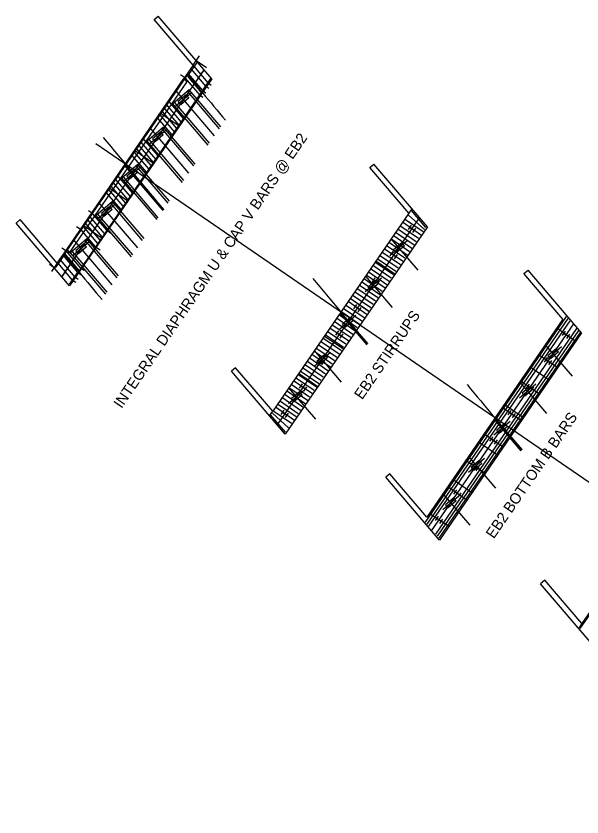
# Model space of a CAD drawing. Extents: x 2378999 to 2381348, y 331302 to 333122.
# Drawn here: x 2379375.1 to 2379481.1, y 331862.8 to 332012.7 of the extents above; entities that cross this region are included whole.
import ezdxf

# ---------------------------------------------------------------- set-up
doc = ezdxf.new("R2010")
doc.units = 0
for name, color, linetype in [('Arrowhead Terminators', 7, 'Continuous'), ('Arrowhead Terminators CELL', 7, 'Continuous'), ('Dimension Lines', 7, 'Continuous'), ('Dimension Lines CELL', 7, 'Continuous'), ('Mis Work Point CELL', 7, 'Continuous'), ('P_NCDOT_Horizontal_Alignment', 7, 'Continuous'), ('P_SMU_Approach_Slab', 7, 'Continuous'), ('P_SMU_Bent_Cap', 7, 'Continuous'), ('P_SMU_Concrete_Barrier_Rail', 7, 'Continuous'), ('P_SMU_D_Deck_Outline', 7, 'Continuous'), ('P_SMU_Deck', 7, 'Continuous'), ('P_SMU_Girder_Concrete', 7, 'Continuous'), ('P_SMU_Mis_L_Lines', 7, 'Continuous'), ('P_SMU_Mis_Long_Chord', 7, 'Continuous'), ('P_SMU_Rebar_B_Bar', 7, 'Continuous'), ('P_SMU_Rebar_K_Bar', 7, 'Continuous'), ('P_SMU_Rebar_U_Bar', 7, 'Continuous'), ('Plan Sheet CELL', 7, 'Continuous'), ('Rebar Lines', 7, 'Continuous'), ('Scratch_Level_0', 7, 'Continuous'), ('Sup Concrete Slab Lines', 7, 'Continuous')]:
    doc.layers.add(name, color=color, linetype=linetype)

msp = doc.modelspace()

# ---------------------------------------------------------------- linework, layer by layer
at = {"layer": 'Arrowhead Terminators'}
for p, q in [((2379451.74, 331917.97), (2379478.16, 331956.43)), ((2379452.06, 331917.6), (2379478.48, 331956.06)), ((2379452.4, 331917.21), (2379478.82, 331955.66)), ((2379480.05, 331954.22), (2379453.63, 331915.77)), ((2379480.38, 331953.83), (2379453.96, 331915.37)), ((2379480.7, 331953.45), (2379454.28, 331915)), ((2379480.71, 331898.07), (2379507.13, 331936.52))]:
    msp.add_line(p, q, dxfattribs=at)
at = {"layer": 'Arrowhead Terminators CELL'}
msp.add_line((2379481.01, 331899), (2379480.43, 331898.15), dxfattribs=at)
at = {"layer": 'Dimension Lines'}
for p, q in [((2379408.29, 332003.47), (2379409.49, 332005.22)), ((2379408.88, 332004.33), (2379410.77, 332003.02)), ((2379406.83, 332001.05), (2379405.95, 332001.66)), ((2379410.65, 331999.55), (2379411.25, 331999.14)), ((2379411.08, 332000.17), (2379411.67, 331999.76)), ((2379409.52, 331997.9), (2379410.12, 331997.5)), ((2379410.09, 331998.73), (2379410.68, 331998.32)), ((2379389.44, 331975.74), (2379388.69, 331976.25)), ((2379451.59, 331972.74), (2379448.6, 331975.44)), ((2379451.86, 331973.13), (2379449.17, 331976.28)), ((2379448.02, 331974.61), (2379451.32, 331972.34)), ((2379387.32, 331972.65), (2379386.43, 331973.26)), ((2379392.13, 331972.59), (2379392.99, 331972.01)), ((2379446.32, 331972.13), (2379449.62, 331969.87)), ((2379446.75, 331972.75), (2379450.04, 331970.49)), ((2379447.17, 331973.37), (2379450.47, 331971.11)), ((2379445.47, 331970.9), (2379448.77, 331968.63)), ((2379445.9, 331971.52), (2379449.2, 331969.25)), ((2379384.58, 331968.67), (2379383.73, 331969.26)), ((2379390.01, 331969.5), (2379390.86, 331968.92)), ((2379444.62, 331969.66), (2379447.92, 331967.4)), ((2379445.05, 331970.28), (2379448.35, 331968.01)), ((2379443.35, 331967.81), (2379446.65, 331965.54)), ((2379443.77, 331968.42), (2379447.07, 331966.16)), ((2379382.26, 331965.59), (2379381.41, 331966.17)), ((2379382.85, 331966.44), (2379381.77, 331964.88)), ((2379442.08, 331965.95), (2379445.37, 331963.69)), ((2379442.5, 331966.57), (2379445.8, 331964.31)), ((2379442.93, 331967.19), (2379446.22, 331964.92)), ((2379386.71, 331964.7), (2379387.3, 331964.29)), ((2379387.27, 331965.52), (2379387.87, 331965.12)), ((2379441.23, 331964.72), (2379444.52, 331962.45)), ((2379441.65, 331965.33), (2379444.95, 331963.07)), ((2379385.72, 331963.26), (2379386.31, 331962.85)), ((2379386.14, 331963.88), (2379386.74, 331963.47)), ((2379440.38, 331963.48), (2379443.67, 331961.21)), ((2379439.1, 331961.63), (2379442.4, 331959.36)), ((2379439.53, 331962.24), (2379442.82, 331959.98)), ((2379439.95, 331962.86), (2379443.25, 331960.6)), ((2379438.25, 331960.39), (2379441.55, 331958.12)), ((2379438.68, 331961.01), (2379441.98, 331958.74)), ((2379436.98, 331958.53), (2379440.28, 331956.27)), ((2379437.83, 331959.77), (2379441.13, 331957.51)), ((2379436.13, 331957.3), (2379439.43, 331955.03)), ((2379436.55, 331957.92), (2379439.85, 331955.65)), ((2379434.86, 331955.44), (2379438.15, 331953.18)), ((2379435.28, 331956.06), (2379438.58, 331953.8)), ((2379435.71, 331956.68), (2379439, 331954.41)), ((2379434.43, 331954.83), (2379437.73, 331952.56)), ((2379433.16, 331952.97), (2379436.45, 331950.71)), ((2379433.58, 331953.59), (2379436.88, 331951.32)), ((2379431.88, 331951.12), (2379435.18, 331948.85)), ((2379432.31, 331951.73), (2379435.6, 331949.47)), ((2379432.73, 331952.35), (2379436.03, 331950.09)), ((2379431.03, 331949.88), (2379434.33, 331947.61)), ((2379431.46, 331950.5), (2379434.76, 331948.23)), ((2379429.76, 331948.03), (2379433.06, 331945.76)), ((2379430.18, 331948.64), (2379433.48, 331946.38)), ((2379428.91, 331946.79), (2379432.21, 331944.52)), ((2379429.33, 331947.41), (2379432.63, 331945.14)), ((2379428.06, 331945.55), (2379431.36, 331943.29)), ((2379428.49, 331946.17), (2379431.78, 331943.91)), ((2379426.79, 331943.7), (2379430.08, 331941.43)), ((2379427.64, 331944.93), (2379430.93, 331942.67)), ((2379425.94, 331942.46), (2379429.23, 331940.2)), ((2379426.36, 331943.08), (2379429.66, 331940.82)), ((2379424.66, 331940.61), (2379427.96, 331938.34)), ((2379425.09, 331941.23), (2379428.38, 331938.96)), ((2379425.51, 331941.84), (2379428.81, 331939.58)), ((2379424.24, 331939.99), (2379427.54, 331937.72)), ((2379425.54, 331934.82), (2379422.85, 331937.97)), ((2379426.11, 331935.65), (2379423.12, 331938.36)), ((2379423.39, 331938.75), (2379426.69, 331936.49))]:
    msp.add_line(p, q, dxfattribs=at)
at = {"layer": 'Dimension Lines CELL'}
msp.add_line((2379573.4, 331862.84), (2379390.08, 331988.78), dxfattribs=at)
at = {"layer": 'Mis Work Point CELL'}
for p, q in [((2379383.72, 331963.88), (2379410.33, 332002.62)), ((2379424.05, 331936.18), (2379450.66, 331974.92)), ((2379452.91, 331916.34), (2379479.53, 331955.08))]:
    msp.add_line(p, q, dxfattribs=at)
at = {"layer": 'P_NCDOT_Horizontal_Alignment'}
msp.add_arc((2384828.54, 336524.76), 7080, 219.900348, 219.972766, dxfattribs=at)
at = {"layer": 'P_SMU_Approach_Slab'}
msp.add_line((2379385.17, 331968.36), (2379407.13, 332000.31), dxfattribs=at)
for radius, start, end in [(7061.33, 219.839771, 219.846793), (7098.67, 219.924281, 219.931263)]:
    msp.add_arc((2384828.54, 336524.76), radius, start, end, dxfattribs=at)
at = {"layer": 'P_SMU_Bent_Cap'}
for p, q in [((2379408, 331998.31), (2379404.96, 331995.71)), ((2379403.21, 331991.34), (2379400.17, 331988.75)), ((2379398.43, 331984.37), (2379395.38, 331981.78)), ((2379393.64, 331977.41), (2379390.6, 331974.81)), ((2379388.85, 331970.44), (2379385.81, 331967.84)), ((2379448.33, 331970.61), (2379445.29, 331968.01)), ((2379443.54, 331963.64), (2379440.5, 331961.04)), ((2379438.75, 331956.67), (2379435.71, 331954.07)), ((2379433.96, 331949.7), (2379430.92, 331947.1)), ((2379477.2, 331950.77), (2379474.15, 331948.17)), ((2379472.41, 331943.8), (2379469.37, 331941.21)), ((2379429.18, 331942.73), (2379426.14, 331940.13)), ((2379467.62, 331936.83), (2379464.58, 331934.24)), ((2379462.83, 331929.87), (2379459.79, 331927.27)), ((2379458.04, 331922.9), (2379455, 331920.3))]:
    msp.add_line(p, q, dxfattribs=at)
at = {"layer": 'P_SMU_Concrete_Barrier_Rail'}
for radius, start, end in [(7060.38, 219.837589, 219.874109), (7060.38, 219.874109, 219.928485), (7099.63, 219.926438, 219.96274), (7099.63, 219.96274, 220.016792)]:
    msp.add_arc((2384828.54, 336524.76), radius, start, end, dxfattribs=at)
at = {"layer": 'P_SMU_D_Deck_Outline'}
for p, q in [((2379407, 331997.95), (2379405.48, 331996.65)), ((2379407.48, 331997.38), (2379407, 331997.95)), ((2379405.96, 331996.08), (2379405.48, 331996.65)), ((2379407.48, 331997.38), (2379405.96, 331996.08)), ((2379402.21, 331990.98), (2379400.69, 331989.68)), ((2379402.7, 331990.41), (2379401.18, 331989.11)), ((2379402.7, 331990.41), (2379402.21, 331990.98)), ((2379401.18, 331989.11), (2379400.69, 331989.68)), ((2379397.42, 331984.01), (2379395.9, 331982.71)), ((2379397.91, 331983.44), (2379397.42, 331984.01)), ((2379396.39, 331982.14), (2379395.9, 331982.71)), ((2379397.91, 331983.44), (2379396.39, 331982.14)), ((2379392.63, 331977.04), (2379391.11, 331975.74)), ((2379393.12, 331976.47), (2379391.6, 331975.17)), ((2379393.12, 331976.47), (2379392.63, 331977.04)), ((2379391.6, 331975.17), (2379391.11, 331975.74)), ((2379387.85, 331970.07), (2379386.33, 331968.77)), ((2379388.33, 331969.5), (2379386.81, 331968.2)), ((2379388.33, 331969.5), (2379387.85, 331970.07)), ((2379447.32, 331970.24), (2379445.8, 331968.94)), ((2379446.29, 331968.37), (2379445.8, 331968.94)), ((2379447.81, 331969.67), (2379446.29, 331968.37)), ((2379447.81, 331969.67), (2379447.32, 331970.24)), ((2379386.81, 331968.2), (2379386.33, 331968.77)), ((2379442.54, 331963.27), (2379441.02, 331961.97)), ((2379443.02, 331962.7), (2379442.54, 331963.27)), ((2379441.5, 331961.4), (2379441.02, 331961.97)), ((2379443.02, 331962.7), (2379441.5, 331961.4)), ((2379437.75, 331956.3), (2379436.23, 331955)), ((2379438.24, 331955.73), (2379436.71, 331954.43)), ((2379438.24, 331955.73), (2379437.75, 331956.3)), ((2379436.71, 331954.43), (2379436.23, 331955)), ((2379476.19, 331950.41), (2379474.67, 331949.11)), ((2379476.68, 331949.84), (2379475.16, 331948.54)), ((2379476.68, 331949.84), (2379476.19, 331950.41)), ((2379432.96, 331949.34), (2379431.44, 331948.04)), ((2379431.93, 331947.47), (2379431.44, 331948.04)), ((2379433.45, 331948.77), (2379431.93, 331947.47)), ((2379433.45, 331948.77), (2379432.96, 331949.34)), ((2379475.16, 331948.54), (2379474.67, 331949.11)), ((2379428.17, 331942.37), (2379426.65, 331941.07)), ((2379428.66, 331941.8), (2379428.17, 331942.37)), ((2379471.4, 331943.44), (2379469.88, 331942.14)), ((2379470.37, 331941.57), (2379469.88, 331942.14)), ((2379471.89, 331942.87), (2379470.37, 331941.57)), ((2379471.89, 331942.87), (2379471.4, 331943.44)), ((2379427.14, 331940.5), (2379426.65, 331941.07)), ((2379428.66, 331941.8), (2379427.14, 331940.5)), ((2379466.62, 331936.47), (2379465.1, 331935.17)), ((2379467.1, 331935.9), (2379466.62, 331936.47)), ((2379465.58, 331934.6), (2379465.1, 331935.17)), ((2379467.1, 331935.9), (2379465.58, 331934.6)), ((2379461.83, 331929.5), (2379460.31, 331928.2)), ((2379462.32, 331928.93), (2379460.8, 331927.63)), ((2379462.32, 331928.93), (2379461.83, 331929.5)), ((2379460.8, 331927.63), (2379460.31, 331928.2)), ((2379457.04, 331922.53), (2379455.52, 331921.23)), ((2379457.53, 331921.96), (2379457.04, 331922.53)), ((2379456.01, 331920.66), (2379455.52, 331921.23)), ((2379457.53, 331921.96), (2379456.01, 331920.66))]:
    msp.add_line(p, q, dxfattribs=at)
at = {"layer": 'P_SMU_Deck'}
for p, q in [((2379407.54, 331998.85), (2379404.5, 331996.25)), ((2379413.21, 331991.58), (2379407.22, 331998.58)), ((2379413.45, 331991.93), (2379407.54, 331998.85)), ((2379411.1, 331988.52), (2379404.5, 331996.25)), ((2379411.35, 331988.88), (2379404.82, 331996.52)), ((2379402.75, 331991.88), (2379399.71, 331989.28)), ((2379408.42, 331984.61), (2379402.44, 331991.61)), ((2379408.66, 331984.97), (2379402.75, 331991.88)), ((2379406.32, 331981.55), (2379399.71, 331989.28)), ((2379406.56, 331981.91), (2379400.03, 331989.55)), ((2379397.96, 331984.91), (2379394.92, 331982.32)), ((2379403.63, 331977.64), (2379397.65, 331984.64)), ((2379403.87, 331978), (2379397.96, 331984.91)), ((2379401.77, 331974.94), (2379395.24, 331982.59)), ((2379401.53, 331974.58), (2379394.92, 331982.32)), ((2379393.18, 331977.94), (2379390.14, 331975.35)), ((2379399.09, 331971.03), (2379393.18, 331977.94)), ((2379398.84, 331970.67), (2379392.86, 331977.67)), ((2379396.74, 331967.62), (2379390.14, 331975.35)), ((2379396.99, 331967.97), (2379390.45, 331975.62)), ((2379388.39, 331970.98), (2379385.35, 331968.38)), ((2379394.05, 331963.7), (2379388.07, 331970.71)), ((2379394.3, 331964.06), (2379388.39, 331970.98)), ((2379391.95, 331960.65), (2379385.35, 331968.38)), ((2379392.2, 331961), (2379385.67, 331968.65))]:
    msp.add_line(p, q, dxfattribs=at)
at = {"layer": 'P_SMU_Girder_Concrete'}
for p, q in [((2379448.56, 331972.72), (2379449.12, 331973.55)), ((2379448.84, 331973.13), (2379449.65, 331972.58)), ((2379449.37, 331972.17), (2379449.93, 331972.99)), ((2379445.16, 331967.78), (2379445.73, 331968.6)), ((2379445.44, 331968.19), (2379446.25, 331967.63)), ((2379445.97, 331967.22), (2379446.54, 331968.04)), ((2379441.76, 331962.83), (2379442.33, 331963.66)), ((2379442.05, 331963.24), (2379442.86, 331962.69)), ((2379442.57, 331962.27), (2379443.14, 331963.1)), ((2379438.36, 331957.89), (2379438.93, 331958.71)), ((2379438.65, 331958.3), (2379439.46, 331957.74)), ((2379439.17, 331957.33), (2379439.74, 331958.15)), ((2379434.97, 331952.94), (2379435.53, 331953.77)), ((2379435.25, 331953.35), (2379436.06, 331952.8)), ((2379435.78, 331952.38), (2379436.34, 331953.21)), ((2379477.43, 331952.89), (2379477.99, 331953.71)), ((2379477.71, 331953.3), (2379478.52, 331952.74)), ((2379478.24, 331952.33), (2379478.8, 331953.16)), ((2379431.57, 331948), (2379432.14, 331948.82)), ((2379431.85, 331948.41), (2379432.66, 331947.85)), ((2379432.38, 331947.44), (2379432.95, 331948.26)), ((2379474.03, 331947.94), (2379474.59, 331948.77)), ((2379474.31, 331948.36), (2379475.12, 331947.8)), ((2379474.84, 331947.39), (2379475.4, 331948.21)), ((2379428.17, 331943.05), (2379428.74, 331943.87)), ((2379428.45, 331943.46), (2379429.27, 331942.91)), ((2379470.63, 331943), (2379471.2, 331943.82)), ((2379428.98, 331942.49), (2379429.55, 331943.32)), ((2379470.91, 331943.41), (2379471.72, 331942.85)), ((2379471.44, 331942.44), (2379472.01, 331943.27)), ((2379424.77, 331938.1), (2379425.34, 331938.93)), ((2379425.06, 331938.52), (2379425.87, 331937.96)), ((2379425.58, 331937.55), (2379426.15, 331938.37)), ((2379467.23, 331938.05), (2379467.8, 331938.88)), ((2379467.52, 331938.46), (2379468.33, 331937.91)), ((2379468.04, 331937.5), (2379468.61, 331938.32)), ((2379463.83, 331933.11), (2379464.4, 331933.93)), ((2379464.12, 331933.52), (2379464.93, 331932.96)), ((2379464.65, 331932.55), (2379465.21, 331933.37)), ((2379460.44, 331928.16), (2379461, 331928.99)), ((2379460.72, 331928.57), (2379461.53, 331928.02)), ((2379461.25, 331927.61), (2379461.81, 331928.43)), ((2379457.04, 331923.22), (2379457.61, 331924.04)), ((2379457.32, 331923.63), (2379458.13, 331923.07)), ((2379457.85, 331922.66), (2379458.42, 331923.48)), ((2379453.64, 331918.27), (2379454.21, 331919.1)), ((2379453.92, 331918.68), (2379454.74, 331918.13)), ((2379454.45, 331917.71), (2379455.02, 331918.54))]:
    msp.add_line(p, q, dxfattribs=at)
at = {"layer": 'P_SMU_Mis_L_Lines'}
for p, q in [((2379412.28, 331990.23), (2379405.02, 331998.72)), ((2379407.49, 331983.26), (2379400.24, 331991.75)), ((2379402.7, 331976.29), (2379395.45, 331984.78)), ((2379397.91, 331969.32), (2379390.66, 331977.81)), ((2379393.13, 331962.35), (2379385.87, 331970.84)), ((2379450.39, 331965.11), (2379445.35, 331971.01)), ((2379445.61, 331958.14), (2379440.56, 331964.04)), ((2379440.82, 331951.17), (2379435.77, 331957.07)), ((2379479.26, 331945.27), (2379474.22, 331951.18)), ((2379436.03, 331944.2), (2379430.99, 331950.11)), ((2379474.47, 331938.31), (2379469.43, 331944.21)), ((2379431.24, 331937.23), (2379426.2, 331943.14)), ((2379469.69, 331931.34), (2379464.64, 331937.24)), ((2379464.9, 331924.37), (2379459.85, 331930.27)), ((2379460.11, 331917.4), (2379455.07, 331923.3))]:
    msp.add_line(p, q, dxfattribs=at)
at = {"layer": 'P_SMU_Mis_Long_Chord'}
for centre, start, end in [((2384828.54, 336524.76), 219.829816, 219.972766), ((2384868.87, 336497.06), 219.816017, 219.945167), ((2384897.73, 336477.22), 219.816017, 219.945167)]:
    msp.add_arc(centre, 7080, start, end, dxfattribs=at)
at = {"layer": 'P_SMU_Rebar_B_Bar'}
for p, q in [((2379400.99, 332012.02), (2379401.75, 332012.66)), ((2379411.79, 332000.92), (2379401.75, 332012.66)), ((2379408.29, 332003.47), (2379400.99, 332012.02)), ((2379408.29, 332003.47), (2379406.57, 332000.97)), ((2379384.62, 331969.02), (2379406.57, 332000.97)), ((2379411.79, 332000.92), (2379385.18, 331962.18)), ((2379405.7, 331992.06), (2379402.13, 331994.51)), ((2379400.89, 331985.05), (2379397.32, 331987.5)), ((2379441.32, 331984.31), (2379442.08, 331984.96)), ((2379448.62, 331975.77), (2379441.32, 331984.31)), ((2379452.12, 331973.21), (2379442.08, 331984.96)), ((2379396.08, 331978.05), (2379392.51, 331980.5)), ((2379449.2, 331976.62), (2379448.62, 331975.77)), ((2379448.62, 331975.77), (2379423.18, 331938.74)), ((2379375.9, 331974.58), (2379375.14, 331973.93)), ((2379385.18, 331962.18), (2379375.14, 331973.93)), ((2379382.85, 331966.44), (2379375.9, 331974.58)), ((2379391.26, 331971.04), (2379387.69, 331973.49)), ((2379452.12, 331973.21), (2379425.5, 331934.47)), ((2379382.85, 331966.44), (2379384.62, 331969.02)), ((2379446.03, 331964.35), (2379442.46, 331966.8)), ((2379470.19, 331964.48), (2379470.95, 331965.12)), ((2379477.49, 331955.94), (2379470.19, 331964.48)), ((2379480.99, 331953.38), (2379470.95, 331965.12)), ((2379441.22, 331957.34), (2379437.65, 331959.8)), ((2379477.49, 331955.94), (2379452.04, 331918.9)), ((2379436.4, 331950.34), (2379432.83, 331952.79)), ((2379480.99, 331953.38), (2379454.37, 331914.64)), ((2379416.23, 331946.87), (2379415.47, 331946.22)), ((2379423.18, 331938.74), (2379416.23, 331946.87)), ((2379474.9, 331944.52), (2379471.33, 331946.97)), ((2379425.5, 331934.47), (2379415.47, 331946.22)), ((2379431.59, 331943.33), (2379428.02, 331945.79)), ((2379470.09, 331937.51), (2379466.51, 331939.97)), ((2379422.59, 331937.88), (2379423.18, 331938.74)), ((2379506.46, 331936.03), (2379481.01, 331899)), ((2379465.27, 331930.51), (2379461.7, 331932.96)), ((2379445.1, 331927.04), (2379444.34, 331926.39)), ((2379452.04, 331918.9), (2379445.1, 331927.04)), ((2379454.37, 331914.64), (2379444.34, 331926.39)), ((2379460.46, 331923.5), (2379456.89, 331925.95)), ((2379474.07, 331907.13), (2379473.31, 331906.48)), ((2379483.34, 331894.74), (2379473.31, 331906.48)), ((2379481.01, 331899), (2379474.07, 331907.13))]:
    msp.add_line(p, q, dxfattribs=at)
at = {"layer": 'P_SMU_Rebar_K_Bar'}
for p, q in [((2379408.95, 332003.99), (2379407.4, 332001.74)), ((2379410.24, 332002.48), (2379408.67, 332000.21)), ((2379411.53, 332000.97), (2379409.95, 331998.68)), ((2379382.53, 331965.54), (2379384.12, 331967.86)), ((2379383.82, 331964.03), (2379385.4, 331966.33)), ((2379386.68, 331964.81), (2379385.11, 331962.52))]:
    msp.add_line(p, q, dxfattribs=at)
at = {"layer": 'P_SMU_Rebar_U_Bar'}
for p, q in [((2379410.65, 331999.55), (2379407.96, 332002.7)), ((2379411.08, 332000.17), (2379408.39, 332003.32)), ((2379409.52, 331997.9), (2379406.83, 332001.05)), ((2379410.09, 331998.73), (2379407.4, 332001.88)), ((2379406.07, 331992.88), (2379403.38, 331996.03)), ((2379406.49, 331993.5), (2379403.8, 331996.65)), ((2379405.22, 331991.65), (2379402.53, 331994.79)), ((2379405.64, 331992.26), (2379402.95, 331995.41)), ((2379404.37, 331990.41), (2379401.68, 331993.56)), ((2379404.79, 331991.03), (2379402.1, 331994.18)), ((2379400.86, 331985.29), (2379398.17, 331988.44)), ((2379401.28, 331985.91), (2379398.59, 331989.06)), ((2379401.71, 331986.53), (2379399.02, 331989.68)), ((2379400.01, 331984.06), (2379397.32, 331987.21)), ((2379400.43, 331984.68), (2379397.74, 331987.83)), ((2379399.58, 331983.44), (2379396.89, 331986.59)), ((2379396.92, 331979.56), (2379394.23, 331982.71)), ((2379396.07, 331978.33), (2379393.38, 331981.47)), ((2379396.49, 331978.94), (2379393.8, 331982.09)), ((2379394.79, 331976.47), (2379392.1, 331979.62)), ((2379395.22, 331977.09), (2379392.53, 331980.24)), ((2379395.64, 331977.71), (2379392.95, 331980.86)), ((2379391.7, 331971.98), (2379389.02, 331975.12)), ((2379392.13, 331972.59), (2379389.44, 331975.74)), ((2379390.86, 331970.74), (2379388.17, 331973.89)), ((2379391.28, 331971.36), (2379388.59, 331974.51)), ((2379390.01, 331969.5), (2379387.32, 331972.65)), ((2379390.43, 331970.12), (2379387.74, 331973.27)), ((2379386.71, 331964.7), (2379384.02, 331967.85)), ((2379387.27, 331965.52), (2379384.58, 331968.67)), ((2379385.72, 331963.26), (2379383.03, 331966.41)), ((2379386.14, 331963.88), (2379383.45, 331967.03))]:
    msp.add_line(p, q, dxfattribs=at)
at = {"layer": 'Plan Sheet CELL'}
for p, q in [((2379400.64, 331979.09), (2379395.59, 331984.99)), ((2379440.97, 331951.38), (2379435.92, 331957.29)), ((2379469.83, 331931.55), (2379464.79, 331937.45))]:
    msp.add_line(p, q, dxfattribs=at)
at = {"layer": 'Rebar Lines'}
for p, q in [((2379451.03, 331971.63), (2379447.46, 331974.08)), ((2379447.63, 331966.68), (2379444.06, 331969.14)), ((2379444.24, 331961.74), (2379440.66, 331964.19)), ((2379440.84, 331956.79), (2379437.27, 331959.25)), ((2379437.44, 331951.85), (2379433.87, 331954.3)), ((2379479.9, 331951.8), (2379476.33, 331954.25)), ((2379434.04, 331946.9), (2379430.47, 331949.36)), ((2379476.5, 331946.85), (2379472.93, 331949.3)), ((2379430.65, 331941.96), (2379427.07, 331944.41)), ((2379473.1, 331941.9), (2379469.53, 331944.36)), ((2379427.25, 331937.01), (2379423.68, 331939.47)), ((2379469.71, 331936.96), (2379466.13, 331939.41)), ((2379466.31, 331932.01), (2379462.74, 331934.47)), ((2379462.91, 331927.07), (2379459.34, 331929.52)), ((2379459.51, 331922.12), (2379455.94, 331924.58)), ((2379456.12, 331917.18), (2379452.54, 331919.63))]:
    msp.add_line(p, q, dxfattribs=at)
at = {"layer": 'Scratch_Level_0'}
for p, q in [((2379384.26, 331968.21), (2379407.15, 332001.52)), ((2379409.81, 331998.33), (2379386.93, 331965.03))]:
    msp.add_line(p, q, dxfattribs=at)
for radius, start, end in [(7060.54, 219.839373, 219.873083), (7099.46, 219.927459, 219.96097)]:
    msp.add_arc((2384828.54, 336524.76), radius, start, end, dxfattribs=at)

# ---------------------------------------------------------------- texts
at = {"layer": 'Sup Concrete Slab Lines'}
for s, p in [('INTEGRAL DIAPHRAGM U & CAP V BARS @ EB2', (2379394.89, 331939.13)), ('EB2 STIRRUPS', (2379439.92, 331940.78)), ('EB2 BOTTOM B BARS', (2379464.55, 331914.76))]:
    msp.add_text(s, height=2, rotation=55.5093, dxfattribs=at).set_placement(p)

doc.saveas('drawing.dxf')
